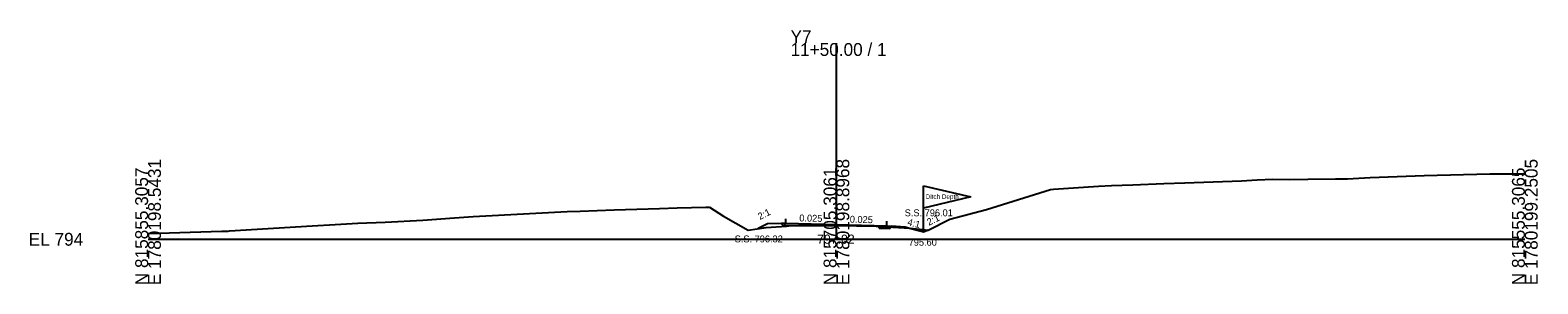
# Model space of a CAD drawing. Extents: x -26 to 2903, y -10 to 5536.
# Drawn here: x -25.7 to 302.8, y 1490.3 to 1545.5 of the extents above; entities that cross this region are included whole.
import ezdxf

# ---------------------------------------------------------------- set-up
doc = ezdxf.new("R2010")
doc.units = 0
for name, color, linetype in [('Exist Cross Section Cell', 7, 'Continuous'), ('Exist XS Center Line Elevation Label', 7, 'Continuous'), ('Exist XS Ground Line', 7, 'Continuous'), ('Prop XS Ditch Slope Text', 7, 'Continuous'), ('Prop XS Ditch Standard Text', 7, 'Continuous'), ('Prop XS Dump Level', 7, 'Continuous'), ('Prop XS Earthwork Shape', 7, 'Continuous'), ('Prop XS EOT Tick Mark', 7, 'Continuous'), ('Prop XS Finish Grade', 7, 'Continuous'), ('Prop XS Finish Grade Earthwork', 7, 'Continuous'), ('Prop XS Finish Grade Pavement', 7, 'Continuous'), ('Prop XS Pvmt Edge Slope', 7, 'Continuous'), ('Prop XS SE Text', 7, 'Continuous'), ('Prop XS Side Slope Text', 7, 'Continuous'), ('Prop XS SS Elevation Text', 7, 'Continuous'), ('Prop XS Subgrade Earthwork', 7, 'Continuous')]:
    doc.layers.add(name, color=color, linetype=linetype)

msp = doc.modelspace()

# ---------------------------------------------------------------- linework, layer by layer
at = {"layer": 'Exist Cross Section Cell'}
for p, q in [((150, 1500), (150, 1542.7)), ((0, 1500), (150, 1500)), ((150, 1500), (300, 1500))]:
    msp.add_line(p, q, dxfattribs=at)
at = {"layer": 'Exist XS Ground Line'}
for p, q in [((197.32, 1510.88), (207.08, 1511.53)), ((207.08, 1511.53), (209.94, 1511.67)), ((209.94, 1511.67), (214.57, 1511.86)), ((214.57, 1511.86), (221.37, 1512.15)), ((221.37, 1512.15), (225.95, 1512.31)), ((225.95, 1512.31), (238.29, 1512.75)), ((238.29, 1512.75), (241.65, 1512.9)), ((241.65, 1512.9), (245.1, 1513.08)), ((245.1, 1513.08), (248.63, 1512.99)), ((248.63, 1512.99), (252.75, 1513.08)), ((252.75, 1513.08), (258.75, 1513.14)), ((258.75, 1513.14), (261.36, 1513.15)), ((261.36, 1513.15), (266.33, 1513.41)), ((266.33, 1513.41), (278.1, 1513.85)), ((278.1, 1513.85), (292.41, 1514.21)), ((292.41, 1514.21), (294.84, 1514.23)), ((294.84, 1514.23), (300, 1514.23)), ((182.72, 1506.47), (196.63, 1510.85)), ((196.63, 1510.85), (197.32, 1510.88)), ((66.8, 1504.68), (70.84, 1504.97)), ((70.84, 1504.97), (73.59, 1505.11)), ((73.59, 1505.11), (91.29, 1506.01)), ((91.29, 1506.01), (94.17, 1506.15)), ((94.17, 1506.15), (101.53, 1506.38)), ((101.53, 1506.38), (111.42, 1506.72)), ((111.42, 1506.72), (115.28, 1506.83)), ((115.28, 1506.83), (121.55, 1507.01)), ((121.55, 1507.01), (122.34, 1507)), ((122.34, 1507), (125.4, 1505.02)), ((125.4, 1505.02), (130.74, 1502.01)), ((174.71, 1504.38), (182.72, 1506.47)), ((0, 1501.25), (16.11, 1501.76)), ((16.11, 1501.76), (17.44, 1501.79)), ((17.44, 1501.79), (17.76, 1501.81)), ((17.76, 1501.81), (35.77, 1502.92)), ((35.77, 1502.92), (40.74, 1503.23)), ((40.74, 1503.23), (45.7, 1503.49)), ((45.7, 1503.49), (51.64, 1503.7)), ((51.64, 1503.7), (59.89, 1504.15)), ((59.89, 1504.15), (66.8, 1504.68)), ((130.74, 1502.01), (134.7, 1502.57)), ((134.7, 1502.57), (139.12, 1502.88)), ((139.12, 1502.88), (140.11, 1503.01)), ((140.11, 1503.01), (140.55, 1503.02)), ((140.55, 1503.02), (141.42, 1503.03)), ((141.42, 1503.03), (150.07, 1503.02)), ((150.07, 1503.02), (158.65, 1502.84)), ((158.65, 1502.84), (159.32, 1502.83)), ((159.32, 1502.83), (159.83, 1502.79)), ((159.83, 1502.79), (165.97, 1502.45)), ((165.97, 1502.45), (168.14, 1502.2)), ((168.14, 1502.2), (169.97, 1501.99)), ((169.97, 1501.99), (174.71, 1504.38))]:
    msp.add_line(p, q, dxfattribs=at)
at = {"layer": 'Prop XS Dump Level'}
for p, q in [((169, 1506.8), (169, 1511.6)), ((169, 1511.6), (179.3, 1509.2)), ((179.3, 1509.2), (169, 1506.8)), ((169, 1501.6), (169, 1506.8)), ((139, 1503.47), (150, 1503.2)), ((150, 1503.2), (161, 1502.92))]:
    msp.add_line(p, q, dxfattribs=at)
at = {"layer": 'Prop XS Earthwork Shape'}
for points in [[(139.44, 1502.92), (139, 1502.93), (138.47, 1502.94), (137.98, 1503.44), (135, 1503.33), (132.98, 1502.32), (134.7, 1502.57), (139.12, 1502.88)], [(139.44, 1502.92), (140.11, 1503.01), (140.55, 1503.02), (140.55, 1502.89)], [(159.32, 1502.42), (161, 1502.38), (161.56, 1502.37), (161.87, 1502.68), (159.83, 1502.79), (159.32, 1502.83)], [(161.87, 1502.68), (165.49, 1502.48), (165, 1502.6), (162.03, 1502.84)], [(165.49, 1502.48), (165.97, 1502.45), (168.14, 1502.2), (169.81, 1502.01), (169, 1501.6)]]:
    msp.add_lwpolyline(points, close=True, dxfattribs=at)
at = {"layer": 'Prop XS EOT Tick Mark'}
for p, q in [((139, 1503.47), (139, 1504.47)), ((161, 1502.92), (161, 1503.92))]:
    msp.add_line(p, q, dxfattribs=at)
at = {"layer": 'Prop XS Finish Grade'}
for p, q in [((139, 1503.47), (137.98, 1503.44)), ((161, 1502.92), (162.03, 1502.84))]:
    msp.add_line(p, q, dxfattribs=at)
at = {"layer": 'Prop XS Finish Grade Earthwork'}
for p, q in [((135, 1503.33), (132.98, 1502.32)), ((137.98, 1503.44), (135, 1503.33)), ((162.03, 1502.84), (165, 1502.6)), ((165, 1502.6), (169, 1501.6)), ((169, 1501.6), (169.81, 1502.01))]:
    msp.add_line(p, q, dxfattribs=at)
at = {"layer": 'Prop XS Finish Grade Pavement'}
for p, q in [((139, 1503.47), (150, 1503.2)), ((150, 1503.2), (161, 1502.92))]:
    msp.add_line(p, q, dxfattribs=at)
at = {"layer": 'Prop XS Pvmt Edge Slope'}
for p, q in [((139, 1503.47), (138.47, 1502.94)), ((161, 1502.92), (161.56, 1502.37))]:
    msp.add_line(p, q, dxfattribs=at)
at = {"layer": 'Prop XS Subgrade Earthwork'}
for p, q in [((138.47, 1502.94), (137.98, 1503.44)), ((139, 1502.93), (138.47, 1502.94)), ((140.55, 1502.89), (139, 1502.93)), ((140.55, 1502.89), (140.55, 1503.02)), ((159.32, 1502.42), (159.32, 1502.83)), ((159.32, 1502.42), (161, 1502.38)), ((161, 1502.38), (161.56, 1502.37)), ((161.56, 1502.37), (162.03, 1502.84))]:
    msp.add_line(p, q, dxfattribs=at)

# ---------------------------------------------------------------- texts
at = {"layer": 'Exist Cross Section Cell'}
for s, p in [('Y7', (140, 1542.7)), ('11+50.00 / 1', (140, 1539.9)), ('EL 794', (-26, 1498.6))]:
    msp.add_text(s, height=2.8, dxfattribs=at).set_placement(p)
for s, p in [('N 815855.3057', (0, 1490)), ('E 1780198.5431', (2.8, 1490)), ('N 815705.3061', (150, 1490)), ('E 1780198.8968', (152.8, 1490)), ('N 815555.3065', (300, 1490)), ('E 1780199.2505', (302.8, 1490))]:
    msp.add_text(s, height=2.8, rotation=90, dxfattribs=at).set_placement(p)
at = {"layer": 'Exist XS Center Line Elevation Label'}
msp.add_text('797.02', height=2, dxfattribs=at).set_placement((145.79, 1499.02))
at = {"layer": 'Prop XS Ditch Slope Text'}
msp.add_text('4:1', height=1.5, rotation=345.9638, dxfattribs=at).set_placement((165.36, 1503.09))
at = {"layer": 'Prop XS Ditch Standard Text'}
msp.add_text('795.60', height=1.5, dxfattribs=at).set_placement((165.74, 1498.6))
at = {"layer": 'Prop XS Dump Level'}
for s, height, p in [('Ditch Depth', 1, (169.44, 1508.77)), ('Case1', 0.04, (135, 1503.29)), ('Eop', 0.3, (140.55, 1502.72)), ('Eop', 0.3, (159.32, 1502.53)), ('Case1', 0.04, (165, 1502.56))]:
    msp.add_text(s, height=height, dxfattribs=at).set_placement(p)
at = {"layer": 'Prop XS SE Text'}
for p in [(141.9, 1503.9), (152.9, 1503.62)]:
    msp.add_text('0.025', height=1.5, rotation=358.5679, dxfattribs=at).set_placement(p)
at = {"layer": 'Prop XS Side Slope Text'}
for p in [(133.32, 1504.17), (170.16, 1502.93)]:
    msp.add_text('2:1', height=1.5, rotation=26.5651, dxfattribs=at).set_placement(p)
at = {"layer": 'Prop XS SS Elevation Text'}
for s, p in [('S.S. 796.01', (164.88, 1505.01)), ('S.S. 796.32', (127.83, 1499.32))]:
    msp.add_text(s, height=1.5, dxfattribs=at).set_placement(p)

doc.saveas('drawing.dxf')
